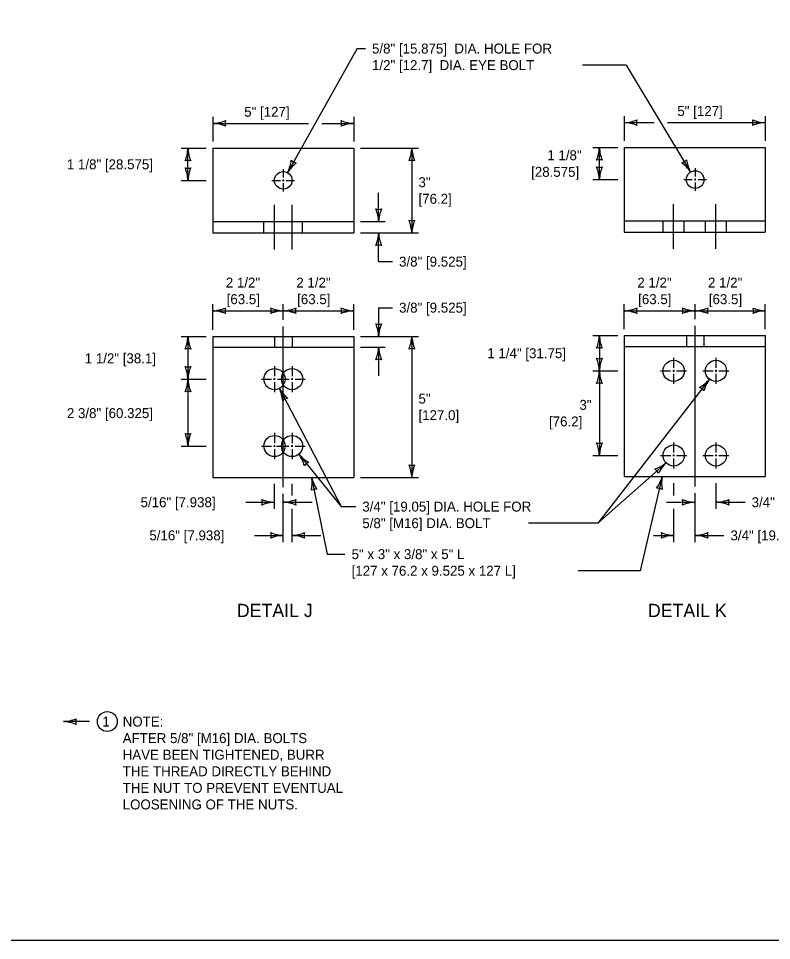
# Model space of a CAD drawing. Extents: x 49991.4 to 50021, y 49987.6 to 50011.4.
# Drawn here: x 50004.17 to 50008.71, y 49987.8 to 49993.36 of the extents above; entities that cross this region are included whole.
import ezdxf

# ---------------------------------------------------------------- set-up
doc = ezdxf.new("R2010")
doc.units = 0
for name, color, linetype in [('Level 1', 7, 'Continuous'), ('Level 2', 7, 'Continuous'), ('Level 3', 7, 'Continuous'), ('Level 4', 7, 'Continuous'), ('Level 5', 7, 'Continuous')]:
    doc.layers.add(name, color=color, linetype=linetype)

msp = doc.modelspace()

# ---------------------------------------------------------------- linework, layer by layer
at = {"layer": 'Level 1'}
for p, q in [((50005.3445, 49992.577), (50005.3445, 49992.067)), ((50005.3445, 49992.577), (50006.1945, 49992.577)), ((50006.1945, 49992.577), (50006.1945, 49992.067)), ((50007.8255, 49992.5816), (50007.8255, 49992.0716)), ((50007.8255, 49992.5816), (50008.6755, 49992.5816)), ((50008.6755, 49992.5816), (50008.6755, 49992.0716)), ((50005.3445, 49992.1351), (50006.1945, 49992.1351)), ((50005.6525, 49992.067), (50005.6525, 49992.1351)), ((50005.8863, 49992.067), (50005.8863, 49992.1351)), ((50007.8255, 49992.1397), (50008.6755, 49992.1397)), ((50008.0593, 49992.0716), (50008.0593, 49992.1397)), ((50008.1868, 49992.0716), (50008.1868, 49992.1397)), ((50008.3142, 49992.0716), (50008.3142, 49992.1397)), ((50008.4417, 49992.0716), (50008.4417, 49992.1397)), ((50005.3445, 49992.067), (50006.1945, 49992.067)), ((50007.8255, 49992.0716), (50008.6755, 49992.0716)), ((50005.3445, 49991.4424), (50005.3445, 49990.5924)), ((50005.3445, 49991.4424), (50006.1945, 49991.4424)), ((50005.7163, 49991.4424), (50005.7163, 49991.378)), ((50005.8225, 49991.4424), (50005.8225, 49991.378)), ((50006.1945, 49991.4424), (50006.1945, 49990.5924)), ((50007.8255, 49991.447), (50007.8255, 49990.597)), ((50007.8255, 49991.447), (50008.6755, 49991.447)), ((50008.1997, 49991.447), (50008.1997, 49991.3825)), ((50008.3059, 49991.447), (50008.3059, 49991.3825)), ((50008.6755, 49991.447), (50008.6755, 49990.597)), ((50005.3445, 49991.378), (50006.1945, 49991.378)), ((50007.8255, 49991.3825), (50008.6755, 49991.3825)), ((50005.3445, 49990.5924), (50006.1945, 49990.5924)), ((50007.8255, 49990.597), (50008.6755, 49990.597))]:
    msp.add_line(p, q, dxfattribs=at)
msp.add_lwpolyline([(49999.3835, 49998.9992), (50016.7501, 49998.9992), (50016.7501, 49987.7988), (49999.3835, 49987.7988)], close=True, dxfattribs=at)
for centre, radius in [((50005.7694, 49992.3837), 0.0531), ((50008.2527, 49992.3883), 0.0531), ((50008.378, 49991.2345), 0.0638), ((50005.7163, 49991.185), 0.0638), ((50005.8225, 49990.7813), 0.0638), ((50008.1231, 49990.7245), 0.0638)]:
    msp.add_circle(centre, radius, dxfattribs=at)
at = {"layer": 'Level 2'}
msp.add_circle((50004.7084, 49989.1196), 0.06, dxfattribs=at)
at = {"layer": 'Level 3'}
for p, q in [((50006.2156, 49993.1786), (50005.7955, 49992.43)), ((50006.2156, 49993.1786), (50006.2643, 49993.1786)), ((50007.8363, 49993.0786), (50007.5741, 49993.0786)), ((50007.8363, 49993.0786), (50008.2253, 49992.4338)), ((50005.3445, 49992.767), (50005.3445, 49992.617)), ((50006.1945, 49992.767), (50006.1945, 49992.617)), ((50007.8255, 49992.7716), (50007.8255, 49992.6216)), ((50008.6755, 49992.7716), (50008.6755, 49992.6216)), ((50005.3445, 49992.727), (50005.9222, 49992.727)), ((50006.0022, 49992.727), (50006.1945, 49992.727)), ((50007.8255, 49992.7316), (50008.0056, 49992.7316)), ((50008.0856, 49992.7316), (50008.6755, 49992.7316)), ((50005.1545, 49992.577), (50005.3045, 49992.577)), ((50005.1945, 49992.3837), (50005.1945, 49992.577)), ((50006.2345, 49992.577), (50006.5845, 49992.577)), ((50006.5445, 49992.577), (50006.5445, 49992.067)), ((50007.6355, 49992.5816), (50007.7855, 49992.5816)), ((50007.6755, 49992.3883), (50007.6755, 49992.5816)), ((50005.1545, 49992.3837), (50005.3045, 49992.3837)), ((50007.6355, 49992.3883), (50007.7855, 49992.3883)), ((50006.3445, 49992.1351), (50006.3445, 49992.3085)), ((50006.2345, 49992.1351), (50006.3845, 49992.1351)), ((50006.2345, 49992.067), (50006.5845, 49992.067)), ((50006.3445, 49991.8936), (50006.3445, 49992.067)), ((50006.3445, 49991.8936), (50006.4275, 49991.8936)), ((50005.3445, 49991.4824), (50005.3445, 49991.637)), ((50005.3445, 49991.597), (50005.7695, 49991.597)), ((50005.7695, 49991.5424), (50005.7695, 49991.637)), ((50005.7695, 49991.597), (50006.1945, 49991.597)), ((50006.1945, 49991.4824), (50006.1945, 49991.637)), ((50006.3445, 49991.6158), (50006.3445, 49991.4424)), ((50006.3445, 49991.6158), (50006.4275, 49991.6158)), ((50007.8255, 49991.487), (50007.8255, 49991.637)), ((50007.8255, 49991.597), (50008.2505, 49991.597)), ((50008.2505, 49991.597), (50008.6755, 49991.597)), ((50008.2524, 49991.547), (50008.2524, 49991.637)), ((50008.6755, 49991.487), (50008.6755, 49991.637)), ((50005.1545, 49991.4424), (50005.3045, 49991.4424)), ((50005.1945, 49991.4424), (50005.1945, 49991.1781)), ((50006.2345, 49991.4424), (50006.5845, 49991.4424)), ((50006.5445, 49991.4424), (50006.5445, 49990.5924)), ((50007.6355, 49991.447), (50007.7855, 49991.447)), ((50007.6755, 49991.447), (50007.6755, 49991.2345)), ((50006.2345, 49991.378), (50006.3845, 49991.378)), ((50006.3445, 49991.378), (50006.3445, 49991.2046)), ((50007.6355, 49991.2345), (50007.7855, 49991.2345)), ((50007.6755, 49991.2345), (50007.6755, 49990.7245)), ((50005.1545, 49991.185), (50005.3045, 49991.185)), ((50005.1945, 49991.1781), (50005.1945, 49990.7813)), ((50005.1545, 49990.7813), (50005.3045, 49990.7813)), ((50005.8627, 49990.7317), (50006.1186, 49990.4161)), ((50007.6355, 49990.7245), (50007.7855, 49990.7245)), ((50008.0775, 49990.6799), (50007.6651, 49990.3161)), ((50006.2345, 49990.5924), (50006.5845, 49990.5924)), ((50005.7162, 49990.4024), (50005.7165, 49990.5524)), ((50005.8224, 49990.4824), (50005.8225, 49990.5524)), ((50008.1251, 49990.4824), (50008.1251, 49990.557)), ((50008.3799, 49990.4024), (50008.3799, 49990.557)), ((50005.7695, 49990.2024), (50005.7695, 49990.4924)), ((50008.2524, 49990.2024), (50008.2524, 49990.497)), ((50005.5428, 49990.4424), (50005.7163, 49990.4424)), ((50005.7695, 49990.4424), (50005.9429, 49990.4424)), ((50008.079, 49990.4424), (50008.2524, 49990.4424)), ((50008.3799, 49990.4424), (50008.5533, 49990.4424)), ((50005.822, 49990.2024), (50005.8222, 49990.4024)), ((50008.1251, 49990.2024), (50008.1251, 49990.4024)), ((50005.596, 49990.2424), (50005.7695, 49990.2424)), ((50005.822, 49990.2424), (50005.9955, 49990.2424)), ((50008.0015, 49990.2424), (50008.1251, 49990.2424)), ((50008.2524, 49990.2424), (50008.4258, 49990.2424)), ((50004.6013, 49989.1196), (50004.4437, 49989.1196))]:
    msp.add_line(p, q, dxfattribs=at)
for points in [[(50008.3389, 49991.1841), (50007.6651, 49990.3161), (50007.2473, 49990.3161)], [(50005.7458, 49991.1285), (50006.1186, 49990.4161), (50006.206, 49990.4161)], [(50005.9405, 49990.5924), (50006.0332, 49990.1292), (50006.1414, 49990.1292)], [(50008.0542, 49990.597), (50007.921, 49990.0292), (50007.5478, 49990.0292)]]:
    msp.add_lwpolyline(points, dxfattribs=at)
for centre, radius, start, end in [((50005.333, 49992.9597), 0.233, 272.8273, 292.0772), ((50005.3353, 49992.5049), 0.2223, 67.456, 87.6395), ((50005.4727, 49992.727), 0.0548, 162.1388, 197.8612), ((50006.2037, 49992.9491), 0.2223, 247.456, 267.6395), ((50006.0663, 49992.727), 0.0548, 342.1388, 17.8612), ((50006.206, 49992.4943), 0.233, 92.8273, 112.0772), ((50007.814, 49992.9643), 0.233, 272.8273, 292.0772), ((50007.8163, 49992.5095), 0.2223, 67.456, 87.6395), ((50007.9537, 49992.7316), 0.0548, 162.1388, 197.8612), ((50008.6847, 49992.9537), 0.2223, 247.456, 267.6395), ((50008.5473, 49992.7316), 0.0548, 342.1388, 17.8612), ((50008.687, 49992.4989), 0.233, 92.8273, 112.0772), ((50004.9724, 49992.5862), 0.2223, 337.456, 357.6395), ((50005.4272, 49992.5885), 0.233, 182.8273, 202.0772), ((50006.3224, 49992.5862), 0.2223, 337.456, 357.6395), ((50006.7772, 49992.5885), 0.233, 182.8273, 202.0772), ((50007.4534, 49992.5908), 0.2223, 337.456, 357.6395), ((50007.9082, 49992.5931), 0.233, 182.8273, 202.0772), ((50005.1945, 49992.4488), 0.0548, 72.1388, 107.8612), ((50005.5867, 49992.5334), 0.233, 333.6461, 352.896), ((50005.9849, 49992.3137), 0.2223, 128.2748, 148.4583), ((50005.858, 49992.5419), 0.0548, 222.9576, 258.68), ((50006.5445, 49992.4488), 0.0548, 72.1388, 107.8612), ((50007.6755, 49992.4534), 0.0548, 72.1388, 107.8612), ((50008.1591, 49992.5436), 0.0548, 283.2409, 318.9633), ((50008.032, 49992.3037), 0.233, 33.9294, 53.1792), ((50008.4202, 49992.5407), 0.2223, 188.5581, 208.7416), ((50005.1945, 49992.5119), 0.0548, 252.1388, 287.8612), ((50004.9618, 49992.3722), 0.233, 2.8273, 22.0772), ((50005.4166, 49992.3745), 0.2223, 157.456, 177.6395), ((50007.6755, 49992.5165), 0.0548, 252.1388, 287.8612), ((50007.4428, 49992.3768), 0.233, 2.8273, 22.0772), ((50007.8976, 49992.3791), 0.2223, 157.456, 177.6395), ((50006.3445, 49992.2633), 0.0548, 252.1388, 287.8612), ((50006.1118, 49992.1236), 0.233, 2.8273, 22.0772), ((50006.5666, 49992.1259), 0.2223, 157.456, 177.6395), ((50006.5445, 49992.1952), 0.0548, 252.1388, 287.8612), ((50006.3118, 49992.0555), 0.233, 2.8273, 22.0772), ((50006.7666, 49992.0578), 0.2223, 157.456, 177.6395), ((50006.1224, 49992.0762), 0.2223, 337.456, 357.6395), ((50006.5772, 49992.0785), 0.233, 182.8273, 202.0772), ((50006.3445, 49991.9388), 0.0548, 72.1388, 107.8612), ((50005.333, 49991.8297), 0.233, 272.8273, 292.0772), ((50005.3353, 49991.3749), 0.2223, 67.456, 87.6395), ((50005.4727, 49991.597), 0.0548, 162.1388, 197.8612), ((50005.7787, 49991.8191), 0.2223, 247.456, 267.6395), ((50005.6413, 49991.597), 0.0548, 342.1388, 17.8612), ((50005.781, 49991.3643), 0.233, 92.8273, 112.0772), ((50005.758, 49991.8297), 0.233, 272.8273, 292.0772), ((50005.7603, 49991.3749), 0.2223, 67.456, 87.6395), ((50005.8977, 49991.597), 0.0548, 162.1388, 197.8612), ((50006.2037, 49991.8191), 0.2223, 247.456, 267.6395), ((50006.0663, 49991.597), 0.0548, 342.1388, 17.8612), ((50006.206, 49991.3643), 0.233, 92.8273, 112.0772), ((50007.814, 49991.8297), 0.233, 272.8273, 292.0772), ((50007.8163, 49991.3749), 0.2223, 67.456, 87.6395), ((50007.9537, 49991.597), 0.0548, 162.1388, 197.8612), ((50008.2616, 49991.8191), 0.2223, 247.456, 267.6395), ((50008.1242, 49991.597), 0.0548, 342.1388, 17.8612), ((50008.2639, 49991.3643), 0.233, 92.8273, 112.0772), ((50008.2409, 49991.8297), 0.233, 272.8273, 292.0772), ((50008.2432, 49991.3749), 0.2223, 67.456, 87.6395), ((50008.3806, 49991.597), 0.0548, 162.1388, 197.8612), ((50008.6844, 49991.813), 0.2162, 247.456, 267.6395), ((50008.5508, 49991.597), 0.0533, 342.1388, 17.8612), ((50008.6867, 49991.3707), 0.2266, 92.8273, 112.0772), ((50006.3445, 49991.5706), 0.0548, 252.1388, 287.8612), ((50006.1118, 49991.4309), 0.233, 2.8273, 22.0772), ((50006.5666, 49991.4332), 0.2223, 157.456, 177.6395), ((50004.9724, 49991.4516), 0.2223, 337.456, 357.6395), ((50005.4272, 49991.4539), 0.233, 182.8273, 202.0772), ((50006.3224, 49991.4516), 0.2223, 337.456, 357.6395), ((50006.7772, 49991.4539), 0.233, 182.8273, 202.0772), ((50007.4534, 49991.4562), 0.2223, 337.456, 357.6395), ((50007.9082, 49991.4585), 0.233, 182.8273, 202.0772), ((50006.1224, 49991.3872), 0.2223, 337.456, 357.6395), ((50006.5772, 49991.3895), 0.233, 182.8273, 202.0772), ((50007.6755, 49991.3188), 0.0548, 72.1388, 107.8612), ((50005.1945, 49991.3142), 0.0548, 72.1388, 107.8612), ((50006.5445, 49991.3142), 0.0548, 72.1388, 107.8612), ((50005.1945, 49991.3132), 0.0548, 252.1388, 287.8612), ((50004.9618, 49991.1735), 0.233, 2.8273, 22.0772), ((50005.4166, 49991.1758), 0.2223, 157.456, 177.6395), ((50006.3445, 49991.2498), 0.0548, 72.1388, 107.8612), ((50007.6755, 49991.3627), 0.0548, 252.1388, 287.8612), ((50007.4428, 49991.223), 0.233, 2.8273, 22.0772), ((50007.8976, 49991.2253), 0.2223, 157.456, 177.6395), ((50007.4534, 49991.2437), 0.2223, 337.456, 357.6395), ((50007.9082, 49991.246), 0.233, 182.8273, 202.0772), ((50004.9724, 49991.1942), 0.2223, 337.456, 357.6395), ((50005.4272, 49991.1965), 0.233, 182.8273, 202.0772), ((50007.6755, 49991.1063), 0.0548, 72.1388, 107.8612), ((50008.169, 49991.3276), 0.2223, 299.6386, 319.8221), ((50008.5298, 49991.0505), 0.233, 145.0099, 164.2597), ((50005.1945, 49991.0568), 0.0548, 72.1388, 107.8612), ((50005.5444, 49991.0345), 0.2223, 4.8683, 25.0519), ((50005.9471, 49991.246), 0.233, 210.2396, 229.4895), ((50008.2603, 49991.0828), 0.0548, 34.3214, 70.0437), ((50005.8048, 49991.0148), 0.0548, 99.5512, 135.2735), ((50005.1945, 49990.9095), 0.0548, 252.1388, 287.8612), ((50004.9618, 49990.7698), 0.233, 2.8273, 22.0772), ((50005.4166, 49990.7721), 0.2223, 157.456, 177.6395), ((50007.6755, 49990.8527), 0.0548, 252.1388, 287.8612), ((50007.4428, 49990.713), 0.233, 2.8273, 22.0772), ((50007.8976, 49990.7153), 0.2223, 157.456, 177.6395), ((50005.6833, 49990.6004), 0.2223, 16.0284, 36.212), ((50006.0375, 49990.8858), 0.233, 221.3997, 240.6496), ((50005.9426, 49990.6315), 0.0548, 110.7113, 146.4336), ((50006.5445, 49990.7206), 0.0548, 252.1388, 287.8612), ((50006.3118, 49990.5809), 0.233, 2.8273, 22.0772), ((50006.7666, 49990.5832), 0.2223, 157.456, 177.6395), ((50007.9374, 49990.8526), 0.2223, 288.8836, 309.0671), ((50008.2402, 49990.5131), 0.233, 134.2549, 153.5047), ((50005.7209, 49990.5578), 0.2223, 348.7675, 8.951), ((50006.1665, 49990.6493), 0.233, 194.1388, 213.3887), ((50007.9814, 49990.5951), 0.0548, 23.5664, 59.2888), ((50007.84, 49990.6566), 0.2223, 324.2547, 344.4383), ((50008.2834, 49990.555), 0.233, 169.626, 188.8759), ((50005.9657, 49990.4667), 0.0548, 83.4503, 119.1727), ((50008.0249, 49990.4722), 0.0548, 58.9376, 94.6599), ((50005.7254, 49990.6645), 0.2223, 247.456, 267.6395), ((50005.5881, 49990.4424), 0.0548, 342.1388, 17.8612), ((50005.7278, 49990.2097), 0.233, 92.8273, 112.0772), ((50005.758, 49990.6751), 0.233, 272.8273, 292.0772), ((50005.7603, 49990.2203), 0.2223, 67.456, 87.6395), ((50005.8977, 49990.4424), 0.0548, 162.1388, 197.8612), ((50008.2616, 49990.6645), 0.2223, 247.456, 267.6395), ((50008.1242, 49990.4424), 0.0548, 342.1388, 17.8612), ((50008.2639, 49990.2097), 0.233, 92.8273, 112.0772), ((50008.3684, 49990.6751), 0.233, 272.8273, 292.0772), ((50008.3707, 49990.2203), 0.2223, 67.456, 87.6395), ((50008.5081, 49990.4424), 0.0548, 162.1388, 197.8612), ((50005.7787, 49990.4645), 0.2223, 247.456, 267.6395), ((50005.6413, 49990.2424), 0.0548, 342.1388, 17.8612), ((50005.8105, 49990.4751), 0.233, 272.8273, 292.0772), ((50005.9503, 49990.2424), 0.0548, 162.1388, 197.8612), ((50008.1343, 49990.4645), 0.2223, 247.456, 267.6395), ((50007.9969, 49990.2424), 0.0548, 342.1388, 17.8612), ((50008.2409, 49990.4751), 0.233, 272.8273, 292.0772), ((50008.3806, 49990.2424), 0.0548, 162.1388, 197.8612), ((50005.781, 49990.0097), 0.233, 92.8273, 112.0772), ((50005.8129, 49990.0203), 0.2223, 67.456, 87.6395), ((50008.1366, 49990.0097), 0.233, 92.8273, 112.0772), ((50008.2432, 49990.0203), 0.2223, 67.456, 87.6395), ((50004.4322, 49989.3523), 0.233, 272.8273, 292.0772), ((50004.4345, 49988.8975), 0.2223, 67.456, 87.6395), ((50004.5719, 49989.1196), 0.0548, 162.1388, 197.8612)]:
    msp.add_arc(centre, radius, start, end, dxfattribs=at)
at = {"layer": 'Level 4'}
for centre in [(50008.1231, 49991.2345), (50005.8225, 49991.185), (50005.7163, 49990.7813), (50008.378, 49990.7243)]:
    msp.add_circle(centre, 0.0638, dxfattribs=at)
at = {"layer": 'Level 5'}
for p, q in [((50005.7695, 49992.4518), (50005.7695, 49992.4014)), ((50008.2527, 49992.4564), (50008.2527, 49992.4059)), ((50005.7014, 49992.3837), (50005.752, 49992.3837)), ((50005.7646, 49992.3837), (50005.7744, 49992.3837)), ((50005.7695, 49992.3893), (50005.7695, 49992.3789)), ((50005.7872, 49992.3837), (50005.8376, 49992.3837)), ((50008.1846, 49992.3883), (50008.2352, 49992.3883)), ((50008.2478, 49992.3883), (50008.2576, 49992.3883)), ((50008.2527, 49992.3939), (50008.2527, 49992.3835)), ((50008.2527, 49992.3703), (50008.2527, 49992.3201)), ((50008.2704, 49992.3883), (50008.3208, 49992.3883)), ((50005.7695, 49992.3657), (50005.7695, 49992.3156)), ((50005.7163, 49991.967), (50005.7163, 49992.2351)), ((50005.8225, 49991.967), (50005.8225, 49992.2351)), ((50008.1231, 49991.9716), (50008.1231, 49992.2397)), ((50008.378, 49991.9716), (50008.378, 49992.2397)), ((50005.7695, 49990.5324), (50005.7695, 49991.5024)), ((50008.2524, 49990.537), (50008.2524, 49991.507)), ((50005.7163, 49991.2638), (50005.7163, 49991.2027)), ((50005.8225, 49991.2638), (50005.8225, 49991.2027)), ((50008.1231, 49991.3132), (50008.1231, 49991.2522)), ((50008.378, 49991.3132), (50008.378, 49991.2522)), ((50008.0435, 49991.2345), (50008.1048, 49991.2345)), ((50008.1182, 49991.2345), (50008.128, 49991.2345)), ((50008.1231, 49991.2401), (50008.1231, 49991.2297)), ((50008.1231, 49991.2165), (50008.1231, 49991.1557)), ((50008.14, 49991.2345), (50008.201, 49991.2345)), ((50008.2992, 49991.2345), (50008.3605, 49991.2345)), ((50008.3731, 49991.2345), (50008.3829, 49991.2345)), ((50008.378, 49991.2401), (50008.378, 49991.2297)), ((50008.378, 49991.2165), (50008.378, 49991.1557)), ((50008.3957, 49991.2345), (50008.4567, 49991.2345)), ((50005.6375, 49991.185), (50005.6988, 49991.185)), ((50005.7114, 49991.185), (50005.7212, 49991.185)), ((50005.7163, 49991.1906), (50005.7163, 49991.1803)), ((50005.7163, 49991.167), (50005.7163, 49991.1063)), ((50005.734, 49991.185), (50005.8051, 49991.185)), ((50005.8176, 49991.185), (50005.8275, 49991.185)), ((50005.8225, 49991.1906), (50005.8225, 49991.1803)), ((50005.8225, 49991.167), (50005.8225, 49991.1063)), ((50005.8403, 49991.185), (50005.9013, 49991.185)), ((50005.7163, 49990.86), (50005.7163, 49990.7989)), ((50005.8225, 49990.86), (50005.8225, 49990.7989)), ((50005.6375, 49990.7813), (50005.6987, 49990.7813)), ((50005.7114, 49990.7813), (50005.7212, 49990.7813)), ((50005.7163, 49990.7869), (50005.7163, 49990.7765)), ((50005.7163, 49990.7632), (50005.7163, 49990.7025)), ((50005.7283, 49990.7813), (50005.805, 49990.7813)), ((50005.8176, 49990.7813), (50005.8275, 49990.7813)), ((50005.8225, 49990.7869), (50005.8225, 49990.7765)), ((50005.8225, 49990.7632), (50005.8225, 49990.7025)), ((50005.8402, 49990.7813), (50005.9013, 49990.7813)), ((50008.1231, 49990.8032), (50008.1231, 49990.7422)), ((50008.378, 49990.803), (50008.378, 49990.742)), ((50008.0443, 49990.7245), (50008.1056, 49990.7245)), ((50008.1182, 49990.7245), (50008.128, 49990.7245)), ((50008.1231, 49990.7301), (50008.1231, 49990.7197)), ((50008.1231, 49990.7065), (50008.1231, 49990.6457)), ((50008.1408, 49990.7245), (50008.2018, 49990.7245)), ((50008.2992, 49990.7243), (50008.3605, 49990.7243)), ((50008.3731, 49990.7243), (50008.3829, 49990.7243)), ((50008.378, 49990.7299), (50008.378, 49990.7195)), ((50008.378, 49990.7063), (50008.378, 49990.6455)), ((50008.3957, 49990.7243), (50008.4567, 49990.7243))]:
    msp.add_line(p, q, dxfattribs=at)

# ---------------------------------------------------------------- texts
at = {"layer": 'Level 2'}
for s, height, p in [('5/8" [15.875]  DIA. HOLE FOR', 0.06, (50006.3043, 49993.1486)), ('1/2" [12.7]  DIA. EYE BOLT', 0.06, (50006.3043, 49993.0486)), ('5" [127]', 0.06, (50005.5338, 49992.767)), ('5" [127]', 0.06, (50008.1453, 49992.7716)), ('1 1/8"', 0.06, (50007.3614, 49992.505)), ('1 1/8" [28.575]', 0.06, (50004.4647, 49992.4503)), ('[28.575]', 0.06, (50007.2637, 49992.405)), ('3"', 0.06, (50006.5845, 49992.3425)), ('[76.2]', 0.06, (50006.5845, 49992.2425)), ('3/8" [9.525]', 0.06, (50006.4675, 49991.8636)), ('2 1/2"', 0.06, (50005.423, 49991.737)), ('2 1/2"', 0.06, (50005.848, 49991.737)), ('2 1/2"', 0.06, (50007.904, 49991.737)), ('2 1/2"', 0.06, (50008.33, 49991.737)), ('[63.5]', 0.06, (50005.428, 49991.637)), ('[63.5]', 0.06, (50005.853, 49991.637)), ('3/8" [9.525]', 0.06, (50006.4675, 49991.5858)), ('[63.5]', 0.06, (50007.909, 49991.637)), ('[63.5]', 0.06, (50008.3351, 49991.637)), ('1 1/4" [31.75]', 0.06, (50006.9996, 49991.3109)), ('1 1/2" [38.1]', 0.06, (50004.5724, 49991.2803)), ('5"', 0.06, (50006.5845, 49991.0374)), ('3"', 0.06, (50007.5548, 49990.9996)), ('2 3/8" [60.325]', 0.06, (50004.4647, 49990.9497)), ('[127.0]', 0.06, (50006.5845, 49990.9374)), ('[76.2]', 0.06, (50007.3714, 49990.8996)), ('5/16" [7.938]', 0.06, (50004.909, 49990.4124)), ('3/4" [19.05] DIA. HOLE FOR  ', 0.06, (50006.246, 49990.3861)), ('3/4" [19.05]', 0.06, (50008.5933, 49990.4124)), ('5/8" [M16] DIA. BOLT', 0.06, (50006.246, 49990.2861)), ('5/16" [7.938]', 0.06, (50004.9621, 49990.2124)), ('3/4" [19.05]', 0.06, (50008.4658, 49990.2124)), ('5" x 3" x 3/8" x 5" L', 0.06, (50006.1814, 49990.0992)), ('[127 x 76.2 x 9.525 x 127 L]', 0.06, (50006.1814, 49989.9992)), ('DETAIL J', 0.08, (50005.4896, 49989.7497)), ('DETAIL K', 0.08, (50007.9679, 49989.7497)), ('1', 0.06, (50004.6786, 49989.0896)), ('NOTE:', 0.06, (50004.8013, 49989.0896)), ('AFTER 5/8" [M16] DIA. BOLTS', 0.06, (50004.8013, 49988.9896)), ('HAVE BEEN TIGHTENED, BURR', 0.06, (50004.8013, 49988.8896)), ('THE THREAD DIRECTLY BEHIND', 0.06, (50004.8013, 49988.7896)), ('THE NUT TO PREVENT EVENTUAL', 0.06, (50004.8013, 49988.6896)), ('LOOSENING OF THE NUTS.', 0.06, (50004.8013, 49988.5896))]:
    msp.add_text(s, height=height, dxfattribs=at).set_placement(p)

doc.saveas('drawing.dxf')
